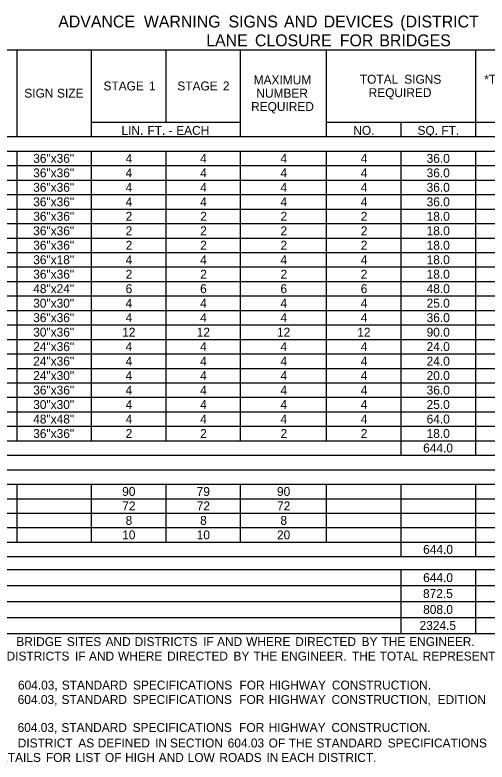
# Model space of a CAD drawing. Extents: x 542596 to 1930787, y -1948294 to 596640.
# Drawn here: x 548589 to 548907, y -1945653 to -1945150 of the extents above; entities that cross this region are included whole.
import ezdxf

# ---------------------------------------------------------------- set-up
doc = ezdxf.new("R2010")
doc.units = 0
doc.layers.add('Default', color=7, linetype='Continuous')

msp = doc.modelspace()

# ---------------------------------------------------------------- linework, layer by layer
at = {"layer": 'Default'}
for p, q in [((548272.08, -1945173.76), (549335.81, -1945173.76)), ((548589.93, -1945232.26), (548589.93, -1945173.76)), ((548640.15, -1945232.26), (548640.15, -1945173.76)), ((548690.36, -1945222.51), (548690.36, -1945173.76)), ((548740.57, -1945232.26), (548740.57, -1945173.76)), ((548798.58, -1945232.26), (548798.58, -1945173.76)), ((548899.01, -1945232.26), (548899.01, -1945173.76)), ((548640.15, -1945222.51), (548740.57, -1945222.51)), ((548740.57, -1945232.26), (548740.57, -1945222.51)), ((548798.58, -1945222.51), (549335.81, -1945222.51)), ((548848.8, -1945232.26), (548848.8, -1945222.51)), ((548899.01, -1945232.26), (548899.01, -1945222.51)), ((548272.08, -1945232.26), (549335.81, -1945232.26)), ((548740.57, -1945232.26), (549335.81, -1945232.26)), ((548272.08, -1945242.01), (549335.81, -1945242.01)), ((548589.93, -1945437.01), (548589.93, -1945242.01)), ((548589.93, -1945437.01), (548589.93, -1945242.01)), ((548640.15, -1945437.01), (548640.15, -1945242.01)), ((548640.15, -1945437.01), (548640.15, -1945242.01)), ((548690.36, -1945427.26), (548690.36, -1945242.01)), ((548690.36, -1945437.01), (548690.36, -1945242.01)), ((548740.57, -1945437.01), (548740.57, -1945242.01)), ((548740.57, -1945437.01), (548740.57, -1945242.01)), ((548798.58, -1945437.01), (548798.58, -1945242.01)), ((548848.8, -1945437.01), (548848.8, -1945242.01)), ((548848.8, -1945446.76), (548848.8, -1945242.01)), ((548899.01, -1945446.76), (548899.01, -1945242.01)), ((548899.01, -1945446.76), (548899.01, -1945242.01)), ((548272.08, -1945251.76), (549335.81, -1945251.76)), ((548272.08, -1945261.51), (549335.81, -1945261.51)), ((548272.08, -1945271.26), (549335.81, -1945271.26)), ((548272.08, -1945281.01), (549335.81, -1945281.01)), ((548272.08, -1945290.76), (549335.81, -1945290.76)), ((548272.08, -1945300.51), (549335.81, -1945300.51)), ((548272.08, -1945310.26), (549335.81, -1945310.26)), ((548272.08, -1945320.01), (549335.81, -1945320.01)), ((548272.08, -1945329.76), (549335.81, -1945329.76)), ((548272.08, -1945339.51), (549335.81, -1945339.51)), ((548272.08, -1945349.26), (549335.81, -1945349.26)), ((548272.08, -1945359.01), (549335.81, -1945359.01)), ((548272.08, -1945368.76), (549335.81, -1945368.76)), ((548272.08, -1945378.51), (549335.81, -1945378.51)), ((548272.08, -1945388.26), (549335.81, -1945388.26)), ((548272.08, -1945398.01), (549335.81, -1945398.01)), ((548272.08, -1945407.76), (549335.81, -1945407.76)), ((548272.08, -1945417.51), (549335.81, -1945417.51)), ((548272.08, -1945427.26), (549335.81, -1945427.26)), ((548272.08, -1945437.01), (548640.15, -1945437.01)), ((548272.08, -1945437.01), (549335.81, -1945437.01)), ((548640.15, -1945437.01), (548690.36, -1945437.01)), ((548690.36, -1945437.01), (548740.57, -1945437.01)), ((548272.08, -1945446.76), (549335.81, -1945446.76)), ((548272.08, -1945456.51), (549335.81, -1945456.51)), ((548272.08, -1945466.26), (549335.81, -1945466.26)), ((548589.93, -1945505.26), (548589.93, -1945466.26)), ((548589.93, -1945505.26), (548589.93, -1945466.26)), ((548640.15, -1945505.26), (548640.15, -1945466.26)), ((548640.15, -1945505.26), (548640.15, -1945466.26)), ((548690.36, -1945505.26), (548690.36, -1945466.26)), ((548690.36, -1945505.26), (548690.36, -1945466.26)), ((548740.57, -1945505.26), (548740.57, -1945466.26)), ((548740.57, -1945505.26), (548740.57, -1945466.26)), ((548798.58, -1945505.26), (548798.58, -1945466.26)), ((548848.8, -1945505.26), (548848.8, -1945466.26)), ((548848.8, -1945515.01), (548848.8, -1945466.26)), ((548899.01, -1945515.01), (548899.01, -1945466.26)), ((548899.01, -1945515.01), (548899.01, -1945466.26)), ((548272.08, -1945476.01), (549335.81, -1945476.01)), ((548272.08, -1945485.76), (549335.81, -1945485.76)), ((548272.08, -1945495.51), (549335.81, -1945495.51)), ((548272.08, -1945505.26), (549264.15, -1945505.26)), ((548272.08, -1945505.26), (548848.8, -1945505.26)), ((548272.08, -1945515.01), (549335.81, -1945515.01)), ((548272.08, -1945523.79), (549335.81, -1945523.79)), ((548272.08, -1945523.79), (549335.81, -1945523.79)), ((548848.8, -1945566.69), (548848.8, -1945523.79)), ((548848.8, -1945566.69), (548848.8, -1945523.79)), ((548899.01, -1945566.69), (548899.01, -1945523.79)), ((548272.08, -1945534.51), (549335.81, -1945534.51)), ((548272.08, -1945545.24), (549335.81, -1945545.24)), ((548272.08, -1945555.96), (549335.81, -1945555.96)), ((548272.08, -1945566.69), (549335.81, -1945566.69))]:
    msp.add_line(p, q, dxfattribs=at)

# ---------------------------------------------------------------- texts
for s, height, p in [(' (DISTRICT', 8, (548845.24, -1945158.75)), ('ADVANCE', 8, (548617.7, -1945158.75)), (' WARNING', 8, (548672.43, -1945158.75)), (' SIGNS', 8, (548729.49, -1945158.75)), (' AND', 8, (548766.84, -1945158.75)), (' DEVICES', 8, (548793.6, -1945158.75)), ('LANE', 8, (548717.41, -1945171.43)), (' CLOSURE', 8, (548747.29, -1945171.43)), (' FOR', 8, (548804.5, -1945171.43)), (' BRIDGES', 8, (548831.14, -1945171.43)), ('TOTAL', 6, (548820.95, -1945196.64)), (' SIGNS', 6, (548848.64, -1945196.64)), ('*TRAFFIC', 6, (548904.77, -1945196.64)), ('STAGE', 6, (548648.2, -1945201.14)), (' 1', 6, (548676.67, -1945201.14)), ('STAGE', 6, (548697.95, -1945201.14)), (' 2', 6, (548726.42, -1945201.14)), ('MAXIMUM', 6, (548749.39, -1945197.01)), ('SIGN', 6, (548594.85, -1945206.01)), (' SIZE', 6, (548614.68, -1945206.01)), ('NUMBER', 6, (548751.2, -1945206.01)), ('REQUIRED', 6, (548826.88, -1945205.64)), ('REQUIRED', 6, (548747.66, -1945215.01)), ('LIN.', 6, (548660.32, -1945231.06)), (' FT.', 6, (548675.58, -1945231.06)), (' EACH', 6, (548694.96, -1945231.06)), ('NO.', 6, (548816.53, -1945231.06)), ('SQ.', 6, (548859.81, -1945231.06)), (' FT.', 6, (548873.67, -1945231.06)), (' -', 6, (548689.9, -1945231.06)), ('36"x36"', 6, (548600.84, -1945249.89)), ('4', 6, (548663.13, -1945249.89)), ('4', 6, (548713.34, -1945249.89)), ('4', 6, (548767.45, -1945249.89)), ('4', 6, (548821.56, -1945249.89)), ('36.0', 6, (548865.95, -1945249.89)), ('36"x36"', 6, (548600.84, -1945259.64)), ('4', 6, (548663.13, -1945259.64)), ('4', 6, (548713.34, -1945259.64)), ('4', 6, (548767.45, -1945259.64)), ('4', 6, (548821.56, -1945259.64)), ('36.0', 6, (548865.95, -1945259.64)), ('36"x36"', 6, (548600.84, -1945269.39)), ('4', 6, (548663.13, -1945269.39)), ('4', 6, (548713.34, -1945269.39)), ('4', 6, (548767.45, -1945269.39)), ('4', 6, (548821.56, -1945269.39)), ('36.0', 6, (548865.95, -1945269.39)), ('36"x36"', 6, (548600.84, -1945279.14)), ('4', 6, (548663.13, -1945279.14)), ('4', 6, (548713.34, -1945279.14)), ('4', 6, (548767.45, -1945279.14)), ('4', 6, (548821.56, -1945279.14)), ('36.0', 6, (548865.95, -1945279.14)), ('36"x36"', 6, (548600.84, -1945288.89)), ('2', 6, (548663.14, -1945288.89)), ('2', 6, (548713.36, -1945288.89)), ('2', 6, (548767.47, -1945288.89)), ('2', 6, (548821.58, -1945288.89)), ('18.0', 6, (548865.95, -1945288.89)), ('36"x36"', 6, (548600.84, -1945298.64)), ('2', 6, (548663.14, -1945298.64)), ('2', 6, (548713.36, -1945298.64)), ('2', 6, (548767.47, -1945298.64)), ('2', 6, (548821.58, -1945298.64)), ('18.0', 6, (548865.95, -1945298.64)), ('36"x36"', 6, (548600.84, -1945308.39)), ('2', 6, (548663.14, -1945308.39)), ('2', 6, (548713.36, -1945308.39)), ('2', 6, (548767.47, -1945308.39)), ('2', 6, (548821.58, -1945308.39)), ('18.0', 6, (548865.95, -1945308.39)), ('36"x18"', 6, (548600.84, -1945318.14)), ('4', 6, (548663.13, -1945318.14)), ('4', 6, (548713.34, -1945318.14)), ('4', 6, (548767.45, -1945318.14)), ('4', 6, (548821.56, -1945318.14)), ('18.0', 6, (548865.95, -1945318.14)), ('36"x36"', 6, (548600.84, -1945327.89)), ('2', 6, (548663.14, -1945327.89)), ('2', 6, (548713.36, -1945327.89)), ('2', 6, (548767.47, -1945327.89)), ('2', 6, (548821.58, -1945327.89)), ('18.0', 6, (548865.95, -1945327.89)), ('48"x24"', 6, (548600.84, -1945337.64)), ('6', 6, (548663.11, -1945337.64)), ('6', 6, (548713.32, -1945337.64)), ('6', 6, (548767.44, -1945337.64)), ('6', 6, (548821.55, -1945337.64)), ('48.0', 6, (548865.95, -1945337.64)), ('30"x30"', 6, (548600.84, -1945347.39)), ('4', 6, (548663.13, -1945347.39)), ('4', 6, (548713.34, -1945347.39)), ('4', 6, (548767.45, -1945347.39)), ('4', 6, (548821.56, -1945347.39)), ('25.0', 6, (548865.95, -1945347.39)), ('36"x36"', 6, (548600.84, -1945357.14)), ('4', 6, (548663.13, -1945357.14)), ('4', 6, (548713.34, -1945357.14)), ('4', 6, (548767.45, -1945357.14)), ('4', 6, (548821.56, -1945357.14)), ('36.0', 6, (548865.95, -1945357.14)), ('30"x36"', 6, (548600.84, -1945366.89)), ('12', 6, (548660.81, -1945366.89)), ('12', 6, (548711.03, -1945366.89)), ('12', 6, (548765.14, -1945366.89)), ('12', 6, (548819.25, -1945366.89)), ('90.0', 6, (548865.95, -1945366.89)), ('24"x36"', 6, (548600.84, -1945376.64)), ('4', 6, (548663.13, -1945376.64)), ('4', 6, (548713.34, -1945376.64)), ('4', 6, (548767.45, -1945376.64)), ('4', 6, (548821.56, -1945376.64)), ('24.0', 6, (548865.95, -1945376.64)), ('24"x36"', 6, (548600.84, -1945386.39)), ('4', 6, (548663.13, -1945386.39)), ('4', 6, (548713.34, -1945386.39)), ('4', 6, (548767.45, -1945386.39)), ('4', 6, (548821.56, -1945386.39)), ('24.0', 6, (548865.95, -1945386.39)), ('24"x30"', 6, (548600.84, -1945396.14)), ('4', 6, (548663.13, -1945396.14)), ('4', 6, (548713.34, -1945396.14)), ('4', 6, (548767.45, -1945396.14)), ('4', 6, (548821.56, -1945396.14)), ('20.0', 6, (548865.95, -1945396.14)), ('36"x36"', 6, (548600.84, -1945405.89)), ('4', 6, (548663.13, -1945405.89)), ('4', 6, (548713.34, -1945405.89)), ('4', 6, (548767.45, -1945405.89)), ('4', 6, (548821.56, -1945405.89)), ('36.0', 6, (548865.95, -1945405.89)), ('30"x30"', 6, (548600.84, -1945415.64)), ('4', 6, (548663.13, -1945415.64)), ('4', 6, (548713.34, -1945415.64)), ('4', 6, (548767.45, -1945415.64)), ('4', 6, (548821.56, -1945415.64)), ('25.0', 6, (548865.95, -1945415.64)), ('48"x48"', 6, (548600.84, -1945425.39)), ('4', 6, (548663.13, -1945425.39)), ('4', 6, (548713.34, -1945425.39)), ('4', 6, (548767.45, -1945425.39)), ('4', 6, (548821.56, -1945425.39)), ('64.0', 6, (548865.95, -1945425.39)), ('36"x36"', 6, (548600.84, -1945435.14)), ('2', 6, (548663.14, -1945435.14)), ('2', 6, (548713.36, -1945435.14)), ('2', 6, (548767.47, -1945435.14)), ('2', 6, (548821.58, -1945435.14)), ('18.0', 6, (548865.95, -1945435.14)), ('644.0', 6, (548863.62, -1945444.89)), ('90', 6, (548660.79, -1945474.14)), ('79', 6, (548710.99, -1945474.14)), ('90', 6, (548765.12, -1945474.14)), ('72', 6, (548660.81, -1945483.89)), ('72', 6, (548711.03, -1945483.89)), ('72', 6, (548765.14, -1945483.89)), ('8', 6, (548663.11, -1945493.64)), ('8', 6, (548713.32, -1945493.64)), ('8', 6, (548767.43, -1945493.64)), ('10', 6, (548660.79, -1945503.39)), ('10', 6, (548711.01, -1945503.39)), ('20', 6, (548765.12, -1945503.39)), ('644.0', 6, (548863.62, -1945513.14)), ('644.0', 6, (548863.62, -1945532.15)), ('872.5', 6, (548863.54, -1945542.88)), ('808.0', 6, (548863.62, -1945553.6)), ('2324.5', 6, (548861.21, -1945564.33)), (' BRIDGE', 6, (548587.23, -1945575.24)), (' SITES', 6, (548621.25, -1945575.24)), (' AND', 6, (548647.37, -1945575.24)), (' DISTRICTS', 6, (548666.95, -1945575.24)), (' IF', 6, (548713.09, -1945575.24)), (' AND', 6, (548722.48, -1945575.24)), (' WHERE', 6, (548742.06, -1945575.24)), (' DIRECTED', 6, (548775.15, -1945575.24)), (' BY', 6, (548819.89, -1945575.24)), (' THE', 6, (548833.34, -1945575.24)), (' ENGINEER.', 6, (548851.99, -1945575.24)), (' DISTRICTS', 6, (548580.65, -1945584.99)), (' IF', 6, (548626.79, -1945584.99)), (' AND', 6, (548636.18, -1945584.99)), (' WHERE', 6, (548655.76, -1945584.99)), (' DIRECTED', 6, (548688.85, -1945584.99)), (' BY', 6, (548733.59, -1945584.99)), (' THE', 6, (548747.04, -1945584.99)), (' ENGINEER.', 6, (548765.69, -1945584.99)), (' THE', 6, (548813.4, -1945584.99)), (' TOTAL', 6, (548832.05, -1945584.99)), (' REPRESENTS', 6, (548861.1, -1945584.99)), (' 604.03,', 6, (548588.32, -1945604.49)), (' STANDARD', 6, (548617.86, -1945604.49)), (' SPECIFICATIONS', 6, (548665.86, -1945604.49)), (' FOR', 6, (548737.62, -1945604.49)), (' HIGHWAY', 6, (548757.54, -1945604.49)), (' CONSTRUCTION.', 6, (548799.86, -1945604.49)), (' 604.03,', 6, (548588.15, -1945614.24)), (' STANDARD', 6, (548617.68, -1945614.24)), (' SPECIFICATIONS', 6, (548665.68, -1945614.24)), (' FOR', 6, (548737.45, -1945614.24)), (' HIGHWAY', 6, (548757.36, -1945614.24)), (' CONSTRUCTION,', 6, (548799.68, -1945614.24)), (' EDITION', 6, (548871.13, -1945614.24)), (' 604.03,', 6, (548588.07, -1945633.06)), (' STANDARD', 6, (548617.61, -1945633.06)), (' SPECIFICATIONS', 6, (548665.61, -1945633.06)), (' FOR', 6, (548737.38, -1945633.06)), (' HIGHWAY', 6, (548757.29, -1945633.06)), (' CONSTRUCTION.', 6, (548799.61, -1945633.06)), (' DISTRICT', 6, (548588.17, -1945643.49)), (' AS', 6, (548628.98, -1945643.49)), (' DEFINED', 6, (548642.06, -1945643.49)), (' IN', 6, (548680.74, -1945643.49)), (' SECTION', 6, (548690.76, -1945643.49)), (' 604.03', 6, (548729.67, -1945643.49)), (' OF', 6, (548757.25, -1945643.49)), (' THE', 6, (548770.83, -1945643.49)), (' STANDARD', 6, (548789.48, -1945643.49)), (' SPECIFICATIONS', 6, (548837.48, -1945643.49)), (' DETAILS', 6, (548570.34, -1945653.24)), (' FOR', 6, (548607.17, -1945653.24)), (' LIST', 6, (548627.08, -1945653.24)), (' OF', 6, (548646.94, -1945653.24)), (' HIGH', 6, (548660.53, -1945653.24)), (' AND', 6, (548683.14, -1945653.24)), (' LOW', 6, (548702.72, -1945653.24)), (' ROADS', 6, (548724.05, -1945653.24)), (' IN', 6, (548755.75, -1945653.24)), (' EACH', 6, (548765.78, -1945653.24)), (' DISTRICT.', 6, (548790.72, -1945653.24))]:
    msp.add_text(s, height=height, dxfattribs=at).set_placement(p)

doc.saveas('drawing.dxf')
